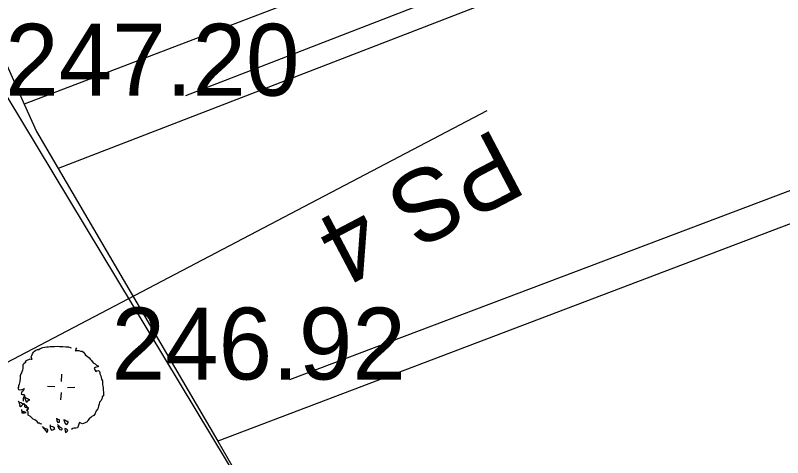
# Model space of a CAD drawing. Extents: x -601754 to -601440, y -1201912 to -1200862.
# Drawn here: x -601616.59 to -601595.26, y -1200952.45 to -1200940.13 of the extents above; entities that cross this region are included whole.
import ezdxf

# ---------------------------------------------------------------- set-up
doc = ezdxf.new("R2010")
doc.units = 0
for name, color, linetype in [('Hranice parcel', 7, 'Continuous'), ('u_hrany', 7, 'Continuous'), ('u_pricne_cesta', 7, 'Continuous'), ('u_vysadba_SO_101', 7, 'Continuous'), ('u_vyska', 7, 'Continuous')]:
    doc.layers.add(name, color=color, linetype=linetype)

msp = doc.modelspace()

# ---------------------------------------------------------------- linework, layer by layer
at = {"layer": 'Hranice parcel'}
for p, q in [((-601620.33, -1200933.7), (-601616.34, -1200942.61)), ((-601615.4, -1200944.4), (-601610.96, -1200951.99)), ((-601610.96, -1200951.99), (-601606.11, -1200960.3))]:
    msp.add_line(p, q, dxfattribs=at)
for points in [[(-601474.14, -1200873.18), (-601548.57, -1200915.94), (-601568.93, -1200924.49), (-601616.34, -1200942.61)], [(-601472.81, -1200874.75), (-601548.9, -1200918.67), (-601615.4, -1200944.4)], [(-601468.497, -1200882.252), (-601546.64, -1200927.52), (-601610.96, -1200951.99)], [(-601616.34, -1200942.61), (-601616, -1200943.37), (-601615.4, -1200944.4)]]:
    msp.add_lwpolyline(points, dxfattribs=at)
at = {"layer": 'u_hrany'}
for points in [[(-601611.85, -1200942.37), (-601592.5, -1200934.86)], [(-601621.22, -1200935.1), (-601608.09, -1200956.91)], [(-601608.96, -1200950.27), (-601589.15, -1200942.77)]]:
    msp.add_lwpolyline(points, dxfattribs=at)
at = {"layer": 'u_pricne_cesta'}
msp.add_lwpolyline([(-601603.486, -1200942.791), (-601621.191, -1200952.092), (-601638.897, -1200961.394)], dxfattribs=at)
at = {"layer": 'u_vysadba_SO_101'}
for points in [[(-601616.302, -1200949.78), (-601616.3, -1200949.751), (-601616.24, -1200949.724), (-601616.21, -1200949.711), (-601616.18, -1200949.698), (-601616.151, -1200949.7), (-601616.122, -1200949.701), (-601616.135, -1200949.671), (-601616.148, -1200949.641), (-601616.131, -1200949.598), (-601616.114, -1200949.555), (-601616.082, -1200949.513), (-601616.052, -1200949.485), (-601616.021, -1200949.458), (-601615.976, -1200949.431), (-601615.932, -1200949.433), (-601615.901, -1200949.406), (-601615.827, -1200949.38), (-601615.767, -1200949.369), (-601615.723, -1200949.356), (-601615.664, -1200949.36), (-601615.62, -1200949.347), (-601615.576, -1200949.35), (-601615.503, -1200949.353), (-601615.429, -1200949.343), (-601615.356, -1200949.347), (-601615.269, -1200949.351), (-601615.181, -1200949.356), (-601615.108, -1200949.36), (-601615.065, -1200949.377), (-601615.036, -1200949.393)], [(-601614.89, -1200949.386), (-601614.906, -1200949.414), (-601614.907, -1200949.443), (-601614.924, -1200949.472), (-601614.879, -1200949.46), (-601614.85, -1200949.461), (-601614.821, -1200949.463), (-601614.777, -1200949.48), (-601614.734, -1200949.482), (-601614.691, -1200949.513), (-601614.664, -1200949.544), (-601614.637, -1200949.59), (-601614.595, -1200949.621), (-601614.539, -1200949.668), (-601614.497, -1200949.714), (-601614.469, -1200949.745), (-601614.429, -1200949.806), (-601614.372, -1200949.838), (-601614.33, -1200949.869), (-601614.286, -1200949.886), (-601614.288, -1200949.915)], [(-601616.302, -1200949.78), (-601616.302, -1200949.794), (-601616.348, -1200949.836), (-601616.379, -1200949.864), (-601616.382, -1200949.907), (-601616.384, -1200949.951), (-601616.387, -1200950.01), (-601616.404, -1200950.053), (-601616.42, -1200950.081), (-601616.436, -1200950.109), (-601616.454, -1200950.167), (-601616.455, -1200950.196), (-601616.458, -1200950.255), (-601616.461, -1200950.299), (-601616.462, -1200950.328), (-601616.481, -1200950.4), (-601616.498, -1200950.443), (-601616.5, -1200950.487), (-601616.516, -1200950.515), (-601616.503, -1200950.545), (-601616.46, -1200950.562), (-601616.371, -1200950.538), (-601616.341, -1200950.524), (-601616.373, -1200950.581), (-601616.404, -1200950.609), (-601616.42, -1200950.637), (-601616.422, -1200950.681), (-601616.393, -1200950.683), (-601616.349, -1200950.685), (-601616.336, -1200950.715), (-601616.353, -1200950.758), (-601616.369, -1200950.787), (-601616.372, -1200950.83), (-601616.374, -1200950.874)], [(-601614.288, -1200949.915), (-601614.333, -1200949.928), (-601614.377, -1200949.94), (-601614.393, -1200949.968), (-601614.38, -1200949.998), (-601614.353, -1200950.044), (-601614.323, -1200950.031), (-601614.279, -1200950.018), (-601614.251, -1200950.049), (-601614.238, -1200950.079), (-601614.24, -1200950.108), (-601614.214, -1200950.168), (-601614.201, -1200950.213), (-601614.189, -1200950.257), (-601614.162, -1200950.303), (-601614.164, -1200950.332), (-601614.166, -1200950.376), (-601614.167, -1200950.405), (-601614.155, -1200950.45), (-601614.144, -1200950.509), (-601614.147, -1200950.567), (-601614.135, -1200950.626), (-601614.137, -1200950.656), (-601614.138, -1200950.685), (-601614.141, -1200950.729), (-601614.171, -1200950.756), (-601614.173, -1200950.785), (-601614.19, -1200950.828), (-601614.206, -1200950.857), (-601614.252, -1200950.898), (-601614.255, -1200950.957), (-601614.273, -1200951.014), (-601614.291, -1200951.087), (-601614.338, -1200951.143), (-601614.371, -1200951.214), (-601614.404, -1200951.271), (-601614.464, -1200951.297), (-601614.494, -1200951.325), (-601614.54, -1200951.366), (-601614.572, -1200951.409), (-601614.589, -1200951.452), (-601614.649, -1200951.478), (-601614.693, -1200951.49), (-601614.723, -1200951.503), (-601614.766, -1200951.486), (-601614.809, -1200951.469), (-601614.826, -1200951.512), (-601614.844, -1200951.57), (-601614.861, -1200951.613), (-601614.906, -1200951.625), (-601614.949, -1200951.623)], [(-601615.302, -1200950.321), (-601615.291, -1200950.117)], [(-601615.486, -1200950.473), (-601615.69, -1200950.462)], [(-601615.135, -1200950.491), (-601614.93, -1200950.487)], [(-601616.323, -1200950.745), (-601616.326, -1200950.789), (-601616.313, -1200950.819), (-601616.3, -1200950.863), (-601616.287, -1200950.893), (-601616.258, -1200950.895), (-601616.242, -1200950.866), (-601616.182, -1200950.84), (-601616.225, -1200950.823), (-601616.253, -1200950.807), (-601616.31, -1200950.775)], [(-601615.318, -1200950.628), (-601615.329, -1200950.832)], [(-601616.505, -1200950.867), (-601616.492, -1200950.897), (-601616.48, -1200950.942), (-601616.467, -1200950.972), (-601616.469, -1200951.001), (-601616.44, -1200951.017), (-601616.409, -1200950.989), (-601616.363, -1200950.948), (-601616.392, -1200950.946), (-601616.435, -1200950.915), (-601616.478, -1200950.898)], [(-601616.348, -1200950.934), (-601616.306, -1200950.98), (-601616.265, -1200951.026), (-601616.223, -1200951.058)], [(-601616.223, -1200951.058), (-601616.252, -1200951.056), (-601616.281, -1200951.055), (-601616.31, -1200951.053), (-601616.323, -1200951.023), (-601616.322, -1200950.994), (-601616.335, -1200950.964)], [(-601616.416, -1200951.106), (-601616.406, -1200951.195), (-601616.362, -1200951.197), (-601616.333, -1200951.198), (-601616.288, -1200951.186), (-601616.346, -1200951.169), (-601616.389, -1200951.166), (-601616.402, -1200951.136)], [(-601615.852, -1200951.517), (-601615.895, -1200951.5), (-601615.923, -1200951.484), (-601615.952, -1200951.482), (-601615.979, -1200951.437), (-601616.008, -1200951.421), (-601616.05, -1200951.389), (-601616.093, -1200951.372), (-601616.134, -1200951.326), (-601616.162, -1200951.295), (-601616.233, -1200951.262), (-601616.231, -1200951.218), (-601616.229, -1200951.175), (-601616.242, -1200951.145), (-601616.27, -1200951.129), (-601616.239, -1200951.086), (-601616.21, -1200951.088)], [(-601615.447, -1200951.348), (-601615.437, -1200951.422), (-601615.41, -1200951.467), (-601615.365, -1200951.455), (-601615.364, -1200951.425), (-601615.362, -1200951.396), (-601615.405, -1200951.379), (-601615.433, -1200951.363)], [(-601615.244, -1200951.388), (-601615.218, -1200951.448), (-601615.206, -1200951.492), (-601615.178, -1200951.523), (-601615.148, -1200951.51), (-601615.117, -1200951.468), (-601615.115, -1200951.439), (-601615.159, -1200951.436), (-601615.188, -1200951.42), (-601615.216, -1200951.404), (-601615.245, -1200951.402)], [(-601615.84, -1200951.576), (-601615.744, -1200951.698), (-601615.717, -1200951.743), (-601615.686, -1200951.701), (-601615.684, -1200951.672), (-601615.712, -1200951.656), (-601615.755, -1200951.639), (-601615.784, -1200951.623), (-601615.812, -1200951.607)], [(-601615.618, -1200951.529), (-601615.622, -1200951.602), (-601615.609, -1200951.647), (-601615.582, -1200951.677), (-601615.523, -1200951.666), (-601615.492, -1200951.638), (-601615.505, -1200951.608), (-601615.548, -1200951.591), (-601615.591, -1200951.574)], [(-601615.413, -1200951.525), (-601615.329, -1200951.603), (-601615.301, -1200951.619), (-601615.287, -1200951.649), (-601615.318, -1200951.677), (-601615.347, -1200951.675), (-601615.36, -1200951.645), (-601615.387, -1200951.6), (-601615.415, -1200951.569)], [(-601615.214, -1200951.638), (-601615.203, -1200951.712), (-601615.19, -1200951.742), (-601615.16, -1200951.729), (-601615.128, -1200951.687), (-601615.156, -1200951.656), (-601615.184, -1200951.64), (-601615.214, -1200951.638)], [(-601614.949, -1200951.623), (-601614.994, -1200951.635), (-601615.025, -1200951.663)]]:
    msp.add_lwpolyline(points, dxfattribs=at)

# ---------------------------------------------------------------- texts
at = {"layer": 'u_pricne_cesta'}
msp.add_text('PS 4', height=2, rotation=207.7145, dxfattribs=at).set_placement((-601603.24, -1200943.258))
at = {"layer": 'u_vyska'}
for s, p in [('247.20', (-601616.87, -1200942.37)), ('246.92', (-601613.914, -1200950.27))]:
    msp.add_text(s, height=2, dxfattribs=at).set_placement(p)

doc.saveas('drawing.dxf')
